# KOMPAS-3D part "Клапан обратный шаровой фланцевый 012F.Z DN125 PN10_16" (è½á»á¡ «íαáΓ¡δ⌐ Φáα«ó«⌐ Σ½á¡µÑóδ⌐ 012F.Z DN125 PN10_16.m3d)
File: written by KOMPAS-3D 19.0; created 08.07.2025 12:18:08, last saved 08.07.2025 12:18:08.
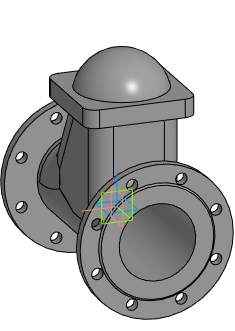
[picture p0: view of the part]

Document properties: Полное имя файла: E:\Dendor Работа Сачек\3D для проектировщиков\5.3 Тип 012F, 012F.Z Клапан обратный шаровой фланцевый\stp_Клапан обратный шаровой фланцевый 012F.Z PN10_16\Клапан обратный шаровой фланцевый 012F.Z DN125 PN10_16.m3d

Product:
- Part/product: Клапан обратный шаровой фланцевый 012F.Z DN125 PN10_16

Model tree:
1. Операция без истории:1  (labels: Клапан обратный шаровой фланцевый 012F.Z DN125 PN10_16)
